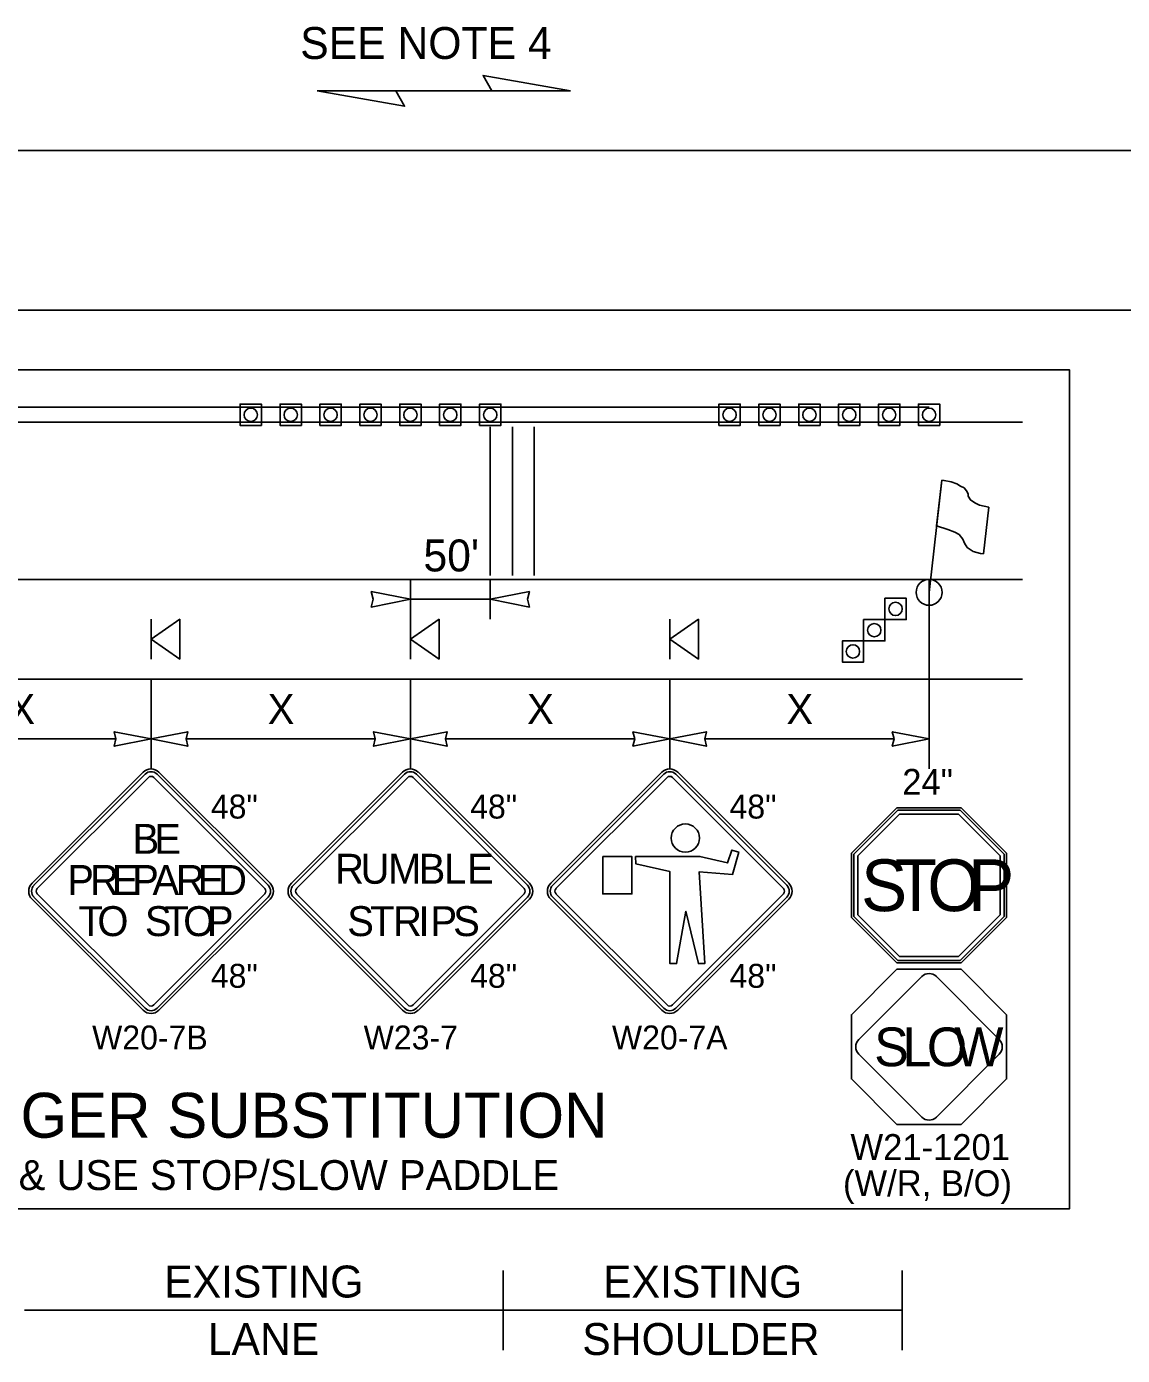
# Model space of a CAD drawing. Extents: x 99999.1 to 100095.7, y 99995 to 100010.7.
# Drawn here: x 100006.496 to 100009.243, y 100003.112 to 100006.443 of the extents above; entities that cross this region are included whole.
import ezdxf

# ---------------------------------------------------------------- set-up
doc = ezdxf.new("R2010")
doc.units = 0
for name, color, linetype in [('RD_ED_ShoulderPavedEdge', 7, 'Continuous'), ('RD_MK_LineDblYellowCenter', 7, 'Continuous'), ('RD_MK_LineEdgeWhite', 7, 'Continuous'), ('RD_MK_LineNoPass', 7, 'Continuous'), ('RD_MK_LineSkipCenter', 7, 'Continuous'), ('SH_DE_DetailHeading2Text', 7, 'Continuous'), ('TR_SN_ConstructionSigns', 7, 'Continuous'), ('TR_WZ_FlaggingStation', 7, 'Continuous'), ('TR_WZ_PortableSignMountBlk-Org', 7, 'Continuous'), ('TR_WZ_TrafficCone', 7, 'Continuous'), ('TR_WZ_WorkZoneDetails', 7, 'Continuous'), ('TR_WZ_WorkZoneTextCurrent', 7, 'Continuous')]:
    doc.layers.add(name, color=color, linetype=linetype)

msp = doc.modelspace()

# ---------------------------------------------------------------- linework, layer by layer
at = {"layer": 'RD_ED_ShoulderPavedEdge'}
for p, q in [((100000.1076, 100005.7323), (100015.6424, 100005.7323)), ((100005.2015, 100004.8073), (100008.9925, 100004.8073))]:
    msp.add_line(p, q, dxfattribs=at)
at = {"layer": 'RD_MK_LineDblYellowCenter'}
for p, q in [((100005.2015, 100005.4886), (100008.0081, 100005.4886)), ((100005.2015, 100005.4511), (100008.0081, 100005.4511))]:
    msp.add_line(p, q, dxfattribs=at)
at = {"layer": 'RD_MK_LineEdgeWhite'}
for p, q in [((100000.1076, 100006.1323), (100015.6424, 100006.1323)), ((100005.2015, 100005.0573), (100008.9925, 100005.0573))]:
    msp.add_line(p, q, dxfattribs=at)
at = {"layer": 'RD_MK_LineNoPass'}
msp.add_line((100008.0081, 100005.4886), (100008.7581, 100005.4886), dxfattribs=at)
at = {"layer": 'RD_MK_LineSkipCenter'}
msp.add_lwpolyline([(100008.9925, 100005.4511), (100008.0081, 100005.4511)], dxfattribs=at)
at = {"layer": 'TR_SN_ConstructionSigns'}
for p, q in [((100006.7882, 100004.5741), (100006.5098, 100004.2957)), ((100006.7932, 100004.5691), (100006.5147, 100004.2907)), ((100006.523, 100004.2824), (100006.8015, 100004.5608)), ((100006.8147, 100004.5608), (100007.0931, 100004.2824)), ((100007.1014, 100004.2907), (100006.823, 100004.5691)), ((100007.1064, 100004.2957), (100006.828, 100004.5741)), ((100007.4382, 100004.5741), (100007.1598, 100004.2957)), ((100007.4432, 100004.5691), (100007.1647, 100004.2907)), ((100007.173, 100004.2824), (100007.4515, 100004.5608)), ((100007.4647, 100004.5608), (100007.7431, 100004.2824)), ((100007.7514, 100004.2907), (100007.473, 100004.5691)), ((100007.7564, 100004.2957), (100007.478, 100004.5741)), ((100008.0882, 100004.5741), (100007.8098, 100004.2957)), ((100008.0932, 100004.5691), (100007.8147, 100004.2907)), ((100007.823, 100004.2824), (100008.1015, 100004.5608)), ((100008.1147, 100004.5608), (100008.3931, 100004.2824)), ((100008.4014, 100004.2907), (100008.123, 100004.5691)), ((100008.4064, 100004.2957), (100008.128, 100004.5741)), ((100008.6775, 100004.4851), (100008.5636, 100004.3713)), ((100008.68, 100004.4791), (100008.5697, 100004.3687)), ((100008.8385, 100004.4851), (100008.6775, 100004.4851)), ((100008.836, 100004.4791), (100008.68, 100004.4791)), ((100008.9463, 100004.3687), (100008.836, 100004.4791)), ((100008.9524, 100004.3713), (100008.8385, 100004.4851)), ((100008.5798, 100004.3646), (100008.6842, 100004.4689)), ((100008.6842, 100004.4689), (100008.8318, 100004.4689)), ((100008.8318, 100004.4689), (100008.9362, 100004.3646)), ((100008.5636, 100004.3713), (100008.5636, 100004.2102)), ((100008.5697, 100004.3687), (100008.5697, 100004.2127)), ((100008.5798, 100004.2169), (100008.5798, 100004.3646)), ((100008.9362, 100004.3646), (100008.9362, 100004.2169)), ((100008.9463, 100004.2127), (100008.9463, 100004.3687)), ((100008.9524, 100004.2102), (100008.9524, 100004.3713)), ((100006.5098, 100004.2559), (100006.7882, 100003.9775)), ((100006.5147, 100004.2609), (100006.7932, 100003.9824)), ((100006.8015, 100003.9907), (100006.523, 100004.2692)), ((100007.0931, 100004.2692), (100006.8147, 100003.9907)), ((100006.823, 100003.9824), (100007.1014, 100004.2609)), ((100006.828, 100003.9775), (100007.1064, 100004.2559)), ((100007.1598, 100004.2559), (100007.4382, 100003.9775)), ((100007.1647, 100004.2609), (100007.4432, 100003.9824)), ((100007.4515, 100003.9907), (100007.173, 100004.2692)), ((100007.7431, 100004.2692), (100007.4647, 100003.9907)), ((100007.473, 100003.9824), (100007.7514, 100004.2609)), ((100007.478, 100003.9775), (100007.7564, 100004.2559)), ((100007.8098, 100004.2559), (100008.0882, 100003.9775)), ((100007.8147, 100004.2609), (100008.0932, 100003.9824)), ((100008.1015, 100003.9907), (100007.823, 100004.2692)), ((100008.3931, 100004.2692), (100008.1147, 100003.9907)), ((100008.123, 100003.9824), (100008.4014, 100004.2609)), ((100008.128, 100003.9775), (100008.4064, 100004.2559)), ((100008.5636, 100004.2102), (100008.6775, 100004.0963)), ((100008.5697, 100004.2127), (100008.68, 100004.1024)), ((100008.6842, 100004.1125), (100008.5798, 100004.2169)), ((100008.9362, 100004.2169), (100008.8318, 100004.1125)), ((100008.836, 100004.1024), (100008.9463, 100004.2127)), ((100008.8385, 100004.0963), (100008.9524, 100004.2102)), ((100008.8318, 100004.1125), (100008.6842, 100004.1125)), ((100008.6775, 100004.0963), (100008.8385, 100004.0963)), ((100008.68, 100004.1024), (100008.836, 100004.1024)), ((100008.7397, 100004.0618), (100008.5819, 100003.9041)), ((100008.9341, 100003.9041), (100008.7763, 100004.0618)), ((100008.5819, 100003.8674), (100008.7397, 100003.7097)), ((100008.7763, 100003.7097), (100008.9341, 100003.8674))]:
    msp.add_line(p, q, dxfattribs=at)
for points in [[(100008.022, 100004.3628), (100008.023, 100004.3447), (100008.1085, 100004.3248), (100008.1085, 100004.0945), (100008.1252, 100004.0945), (100008.1487, 100004.2254), (100008.1799, 100004.0945), (100008.1957, 100004.0945), (100008.1819, 100004.3247), (100008.2654, 100004.318), (100008.2812, 100004.3738), (100008.264, 100004.3787), (100008.2529, 100004.3468), (100008.1839, 100004.3628)], [(100007.9404, 100004.3626), (100007.9404, 100004.269), (100008.0134, 100004.269), (100008.0134, 100004.3626)], [(100008.9524, 100003.9663), (100008.9524, 100003.8052), (100008.8385, 100003.6913), (100008.6775, 100003.6913), (100008.5636, 100003.8052), (100008.5636, 100003.9663), (100008.6775, 100004.0801), (100008.8385, 100004.0801)]]:
    msp.add_lwpolyline(points, close=True, dxfattribs=at)
msp.add_circle((100008.1472, 100004.4091), 0.0354, dxfattribs=at)
for centre, radius, start, end in [((100006.8081, 100004.5542), 0.0281, 45, 135), ((100006.8081, 100004.5542), 0.0211, 45, 135), ((100007.4581, 100004.5542), 0.0281, 45, 135), ((100007.4581, 100004.5542), 0.0211, 45, 135), ((100008.1081, 100004.5542), 0.0281, 45, 135), ((100008.1081, 100004.5542), 0.0211, 45, 135), ((100006.8081, 100004.5542), 0.00938, 45, 135), ((100007.4581, 100004.5542), 0.00938, 45, 135), ((100008.1081, 100004.5542), 0.00938, 45, 135), ((100006.5297, 100004.2758), 0.0281, 135, 225), ((100006.5297, 100004.2758), 0.0211, 135, 225), ((100006.5297, 100004.2758), 0.00938, 135, 225), ((100007.0865, 100004.2758), 0.00938, 315, 45), ((100007.0865, 100004.2758), 0.0211, 315, 45), ((100007.0865, 100004.2758), 0.0281, 315, 45), ((100007.1797, 100004.2758), 0.0281, 135, 225), ((100007.1797, 100004.2758), 0.0211, 135, 225), ((100007.1797, 100004.2758), 0.00938, 135, 225), ((100007.7365, 100004.2758), 0.00938, 315, 45), ((100007.7365, 100004.2758), 0.0211, 315, 45), ((100007.7365, 100004.2758), 0.0281, 315, 45), ((100007.8297, 100004.2758), 0.0281, 135, 225), ((100007.8297, 100004.2758), 0.0211, 135, 225), ((100007.8297, 100004.2758), 0.00938, 135, 225), ((100008.3865, 100004.2758), 0.00938, 315, 45), ((100008.3865, 100004.2758), 0.0211, 315, 45), ((100008.3865, 100004.2758), 0.0281, 315, 45), ((100008.758, 100004.0435), 0.0259, 45, 135), ((100006.8081, 100003.9974), 0.0281, 225, 315), ((100006.8081, 100003.9974), 0.0211, 225, 315), ((100006.8081, 100003.9974), 0.00938, 225, 315), ((100007.4581, 100003.9974), 0.0281, 225, 315), ((100007.4581, 100003.9974), 0.0211, 225, 315), ((100007.4581, 100003.9974), 0.00938, 225, 315), ((100008.1081, 100003.9974), 0.0281, 225, 315), ((100008.1081, 100003.9974), 0.0211, 225, 315), ((100008.1081, 100003.9974), 0.00938, 225, 315), ((100008.6003, 100003.8857), 0.0259, 135, 225), ((100008.9157, 100003.8857), 0.0259, 315, 45), ((100008.758, 100003.728), 0.0259, 225, 315)]:
    msp.add_arc(centre, radius, start, end, dxfattribs=at)
at = {"layer": 'TR_WZ_FlaggingStation'}
for p, q in [((100008.7581, 100005.0248), (100008.7901, 100005.3058)), ((100008.7771, 100005.1917), (100008.7902, 100005.3061)), ((100008.9081, 100005.2383), (100008.8948, 100005.1211)), ((100008.7771, 100005.1917), (100008.7771, 100005.1917))]:
    msp.add_line(p, q, dxfattribs=at)
for points in [[(100008.7902, 100005.3061), (100008.7959, 100005.3048), (100008.8137, 100005.3014), (100008.8276, 100005.2972), (100008.8372, 100005.2911), (100008.8458, 100005.2864), (100008.8515, 100005.2796), (100008.8557, 100005.2717), (100008.8562, 100005.2655), (100008.8616, 100005.2563), (100008.8724, 100005.2489), (100008.8848, 100005.2437), (100008.9081, 100005.2383)], [(100008.8948, 100005.1211), (100008.8867, 100005.1225), (100008.869, 100005.1271), (100008.8533, 100005.1376), (100008.8468, 100005.1482), (100008.8429, 100005.1585), (100008.8338, 100005.1694), (100008.8229, 100005.1756), (100008.8055, 100005.1827), (100008.7771, 100005.1917)]]:
    msp.add_lwpolyline(points, dxfattribs=at)
msp.add_circle((100008.7581, 100005.0248), 0.0325, dxfattribs=at)
at = {"layer": 'TR_WZ_PortableSignMountBlk-Org'}
for p, q in [((100006.8081, 100004.8574), (100006.8081, 100004.9574)), ((100007.4581, 100004.8574), (100007.4581, 100004.9574)), ((100008.1081, 100004.8574), (100008.1081, 100004.9574))]:
    msp.add_line(p, q, dxfattribs=at)
for points in [[(100006.8081, 100004.9073), (100006.8799, 100004.9574), (100006.8799, 100004.8574)], [(100007.4581, 100004.9073), (100007.5299, 100004.9574), (100007.5299, 100004.8574)], [(100008.1081, 100004.9073), (100008.1799, 100004.9574), (100008.1799, 100004.8574)]]:
    msp.add_lwpolyline(points, close=True, dxfattribs=at)
at = {"layer": 'TR_WZ_TrafficCone'}
for points in [[(100007.0848, 100005.4965), (100007.0314, 100005.4965), (100007.0314, 100005.4432), (100007.0848, 100005.4432), (100007.0848, 100005.4965)], [(100007.0848, 100005.4432), (100007.0314, 100005.4432), (100007.0314, 100005.4965), (100007.0848, 100005.4965), (100007.0848, 100005.4432)], [(100007.1848, 100005.4965), (100007.1314, 100005.4965), (100007.1314, 100005.4432), (100007.1848, 100005.4432), (100007.1848, 100005.4965)], [(100007.1848, 100005.4432), (100007.1314, 100005.4432), (100007.1314, 100005.4965), (100007.1848, 100005.4965), (100007.1848, 100005.4432)], [(100007.2848, 100005.4965), (100007.2314, 100005.4965), (100007.2314, 100005.4432), (100007.2848, 100005.4432), (100007.2848, 100005.4965)], [(100007.2848, 100005.4432), (100007.2314, 100005.4432), (100007.2314, 100005.4965), (100007.2848, 100005.4965), (100007.2848, 100005.4432)], [(100007.3848, 100005.4965), (100007.3314, 100005.4965), (100007.3314, 100005.4432), (100007.3848, 100005.4432), (100007.3848, 100005.4965)], [(100007.3848, 100005.4432), (100007.3314, 100005.4432), (100007.3314, 100005.4965), (100007.3848, 100005.4965), (100007.3848, 100005.4432)], [(100007.4848, 100005.4965), (100007.4314, 100005.4965), (100007.4314, 100005.4432), (100007.4848, 100005.4432), (100007.4848, 100005.4965)], [(100007.4848, 100005.4432), (100007.4314, 100005.4432), (100007.4314, 100005.4965), (100007.4848, 100005.4965), (100007.4848, 100005.4432)], [(100007.5848, 100005.4965), (100007.5314, 100005.4965), (100007.5314, 100005.4432), (100007.5848, 100005.4432), (100007.5848, 100005.4965)], [(100007.5848, 100005.4432), (100007.5314, 100005.4432), (100007.5314, 100005.4965), (100007.5848, 100005.4965), (100007.5848, 100005.4432)], [(100007.6848, 100005.4965), (100007.6314, 100005.4965), (100007.6314, 100005.4432), (100007.6848, 100005.4432), (100007.6848, 100005.4965)], [(100007.6848, 100005.4432), (100007.6314, 100005.4432), (100007.6314, 100005.4965), (100007.6848, 100005.4965), (100007.6848, 100005.4432)], [(100008.2848, 100005.4965), (100008.2314, 100005.4965), (100008.2314, 100005.4432), (100008.2848, 100005.4432), (100008.2848, 100005.4965)], [(100008.2848, 100005.4432), (100008.2314, 100005.4432), (100008.2314, 100005.4965), (100008.2848, 100005.4965), (100008.2848, 100005.4432)], [(100008.3848, 100005.4965), (100008.3314, 100005.4965), (100008.3314, 100005.4432), (100008.3848, 100005.4432), (100008.3848, 100005.4965)], [(100008.3848, 100005.4432), (100008.3314, 100005.4432), (100008.3314, 100005.4965), (100008.3848, 100005.4965), (100008.3848, 100005.4432)], [(100008.4848, 100005.4965), (100008.4314, 100005.4965), (100008.4314, 100005.4432), (100008.4848, 100005.4432), (100008.4848, 100005.4965)], [(100008.4848, 100005.4432), (100008.4314, 100005.4432), (100008.4314, 100005.4965), (100008.4848, 100005.4965), (100008.4848, 100005.4432)], [(100008.5848, 100005.4965), (100008.5314, 100005.4965), (100008.5314, 100005.4432), (100008.5848, 100005.4432), (100008.5848, 100005.4965)], [(100008.5848, 100005.4432), (100008.5314, 100005.4432), (100008.5314, 100005.4965), (100008.5848, 100005.4965), (100008.5848, 100005.4432)], [(100008.6848, 100005.4965), (100008.6314, 100005.4965), (100008.6314, 100005.4432), (100008.6848, 100005.4432), (100008.6848, 100005.4965)], [(100008.6848, 100005.4432), (100008.6314, 100005.4432), (100008.6314, 100005.4965), (100008.6848, 100005.4965), (100008.6848, 100005.4432)], [(100008.7848, 100005.4965), (100008.7314, 100005.4965), (100008.7314, 100005.4432), (100008.7848, 100005.4432), (100008.7848, 100005.4965)], [(100008.7848, 100005.4432), (100008.7314, 100005.4432), (100008.7314, 100005.4965), (100008.7848, 100005.4965), (100008.7848, 100005.4432)], [(100008.6474, 100005.01), (100008.7008, 100005.01), (100008.7008, 100004.9567), (100008.6474, 100004.9567), (100008.6474, 100005.01)], [(100008.6474, 100004.9567), (100008.7008, 100004.9567), (100008.7008, 100005.01), (100008.6474, 100005.01), (100008.6474, 100004.9567)], [(100008.5941, 100004.9567), (100008.6474, 100004.9567), (100008.6474, 100004.9033), (100008.5941, 100004.9033), (100008.5941, 100004.9567)], [(100008.5941, 100004.9033), (100008.6474, 100004.9033), (100008.6474, 100004.9567), (100008.5941, 100004.9567), (100008.5941, 100004.9033)], [(100008.5408, 100004.9033), (100008.5941, 100004.9033), (100008.5941, 100004.85), (100008.5408, 100004.85), (100008.5408, 100004.9033)], [(100008.5408, 100004.85), (100008.5941, 100004.85), (100008.5941, 100004.9033), (100008.5408, 100004.9033), (100008.5408, 100004.85)]]:
    msp.add_lwpolyline(points, dxfattribs=at)
for centre in [(100007.0581, 100005.4698), (100007.1581, 100005.4698), (100007.2581, 100005.4698), (100007.3581, 100005.4698), (100007.4581, 100005.4698), (100007.5581, 100005.4698), (100007.6581, 100005.4698), (100008.2581, 100005.4698), (100008.3581, 100005.4698), (100008.4581, 100005.4698), (100008.5581, 100005.4698), (100008.6581, 100005.4698), (100008.7581, 100005.4698), (100008.6741, 100004.9833), (100008.6208, 100004.93), (100008.5674, 100004.8767)]:
    msp.add_circle(centre, 0.0167, dxfattribs=at)
at = {"layer": 'TR_WZ_WorkZoneDetails'}
for p, q in [((100007.4213, 100006.2816), (100007.6624, 100006.2816)), ((100007.6624, 100006.2816), (100007.4213, 100006.2816)), ((100007.6581, 100005.0673), (100007.6581, 100005.4398)), ((100007.7137, 100005.0673), (100007.7137, 100005.4398)), ((100007.7686, 100005.0673), (100007.7686, 100005.4398)), ((100007.4581, 100004.9574), (100007.4581, 100005.0573)), ((100007.6581, 100005.0573), (100007.6581, 100004.9574)), ((100008.7581, 100005.0573), (100008.7581, 100004.5823)), ((100007.6581, 100005.0074), (100007.4581, 100005.0074)), ((100006.8081, 100004.8073), (100006.8081, 100004.5823)), ((100007.4581, 100004.8073), (100007.4581, 100004.5823)), ((100008.1081, 100004.8073), (100008.1081, 100004.5823)), ((100006.7202, 100004.6573), (100006.246, 100004.6573)), ((100007.3702, 100004.6573), (100006.896, 100004.6573)), ((100008.0202, 100004.6573), (100007.546, 100004.6573)), ((100008.6702, 100004.6573), (100008.196, 100004.6573)), ((100007.6907, 100003.1255), (100007.6907, 100003.3255)), ((100008.6907, 100003.1255), (100008.6907, 100003.3255)), ((100006.4907, 100003.2255), (100007.6907, 100003.2255)), ((100007.6907, 100003.2255), (100008.6907, 100003.2255))]:
    msp.add_line(p, q, dxfattribs=at)
for points in [[(100007.859, 100006.2816), (100007.6401, 100006.3202), (100007.6624, 100006.2816)], [(100007.2248, 100006.2816), (100007.4436, 100006.243), (100007.4213, 100006.2816)], [(100007.4581, 100005.0074), (100007.3598, 100004.9881), (100007.3644, 100005.0074), (100007.3598, 100005.0267)], [(100007.6581, 100005.0074), (100007.7564, 100004.9881), (100007.7518, 100005.0074), (100007.7564, 100005.0267)], [(100006.8081, 100004.6573), (100006.7159, 100004.6754), (100006.7202, 100004.6573), (100006.7159, 100004.6393)], [(100006.8081, 100004.6573), (100006.9002, 100004.6754), (100006.896, 100004.6573), (100006.9002, 100004.6393)], [(100007.4581, 100004.6573), (100007.3659, 100004.6754), (100007.3702, 100004.6573), (100007.3659, 100004.6393)], [(100007.4581, 100004.6573), (100007.5502, 100004.6754), (100007.546, 100004.6573), (100007.5502, 100004.6393)], [(100008.1081, 100004.6573), (100008.0159, 100004.6754), (100008.0202, 100004.6573), (100008.0159, 100004.6393)], [(100008.1081, 100004.6573), (100008.2002, 100004.6754), (100008.196, 100004.6573), (100008.2002, 100004.6393)], [(100008.7581, 100004.6573), (100008.6659, 100004.6754), (100008.6702, 100004.6573), (100008.6659, 100004.6393)]]:
    msp.add_lwpolyline(points, close=True, dxfattribs=at)
at = {"layer": 'TR_WZ_WorkZoneTextCurrent'}
msp.add_lwpolyline([(100005.1015, 100005.5823), (100009.1102, 100005.5823), (100009.1102, 100003.4799), (100005.1015, 100003.4799)], close=True, dxfattribs=at)

# ---------------------------------------------------------------- texts
at = {"layer": 'SH_DE_DetailHeading2Text'}
msp.add_text('HUMAN FLAGGER SUBSTITUTION', height=0.1125, rotation=360, dxfattribs=at).set_placement((100005.4946, 100003.658))
at = {"layer": 'TR_SN_ConstructionSigns'}
for s, height, p in [('24"', 0.0648, (100008.6908, 100004.5175)), ('B', 0.075, (100006.7616, 100004.3695)), ('E', 0.075, (100006.8163, 100004.3695)), ('R', 0.075, (100007.2695, 100004.2945)), ('U', 0.075, (100007.3332, 100004.2945)), ('M', 0.075, (100007.4022, 100004.2945)), ('B', 0.075, (100007.4787, 100004.2945)), ('L', 0.075, (100007.5425, 100004.2945)), ('E', 0.075, (100007.6002, 100004.2945)), ('S', 0.1296, (100008.5876, 100004.2259)), ('T', 0.1296, (100008.6718, 100004.2259)), ('O', 0.1296, (100008.7535, 100004.2259)), ('P', 0.1296, (100008.8559, 100004.2259)), ('P', 0.075, (100006.5981, 100004.2664)), ('R', 0.075, (100006.6551, 100004.2664)), ('E', 0.075, (100006.7098, 100004.2664)), ('P', 0.075, (100006.7608, 100004.2664)), ('A', 0.075, (100006.8118, 100004.2664)), ('R', 0.075, (100006.8703, 100004.2664)), ('E', 0.075, (100006.9251, 100004.2664)), ('D', 0.075, (100006.9761, 100004.2664)), ('T', 0.075, (100006.6262, 100004.1633)), ('O', 0.075, (100006.6735, 100004.1633)), ('S', 0.075, (100006.7927, 100004.1633)), ('T', 0.075, (100006.8415, 100004.1633)), ('O', 0.075, (100006.8887, 100004.1633)), ('P', 0.075, (100006.948, 100004.1633)), ('S', 0.075, (100007.2998, 100004.1633)), ('T', 0.075, (100007.3568, 100004.1633)), ('R', 0.075, (100007.4146, 100004.1633)), ('I', 0.075, (100007.4783, 100004.1633)), ('P', 0.075, (100007.5083, 100004.1633)), ('S', 0.075, (100007.5653, 100004.1633)), ('S', 0.0972, (100008.6205, 100003.8371)), ('L', 0.0972, (100008.6914, 100003.8371)), ('O', 0.0972, (100008.7527, 100003.8371)), ('W', 0.0972, (100008.8217, 100003.8371))]:
    msp.add_text(s, height=height, dxfattribs=at).set_placement(p)
for s, height, p in [('48"', 0.06, (100006.9579, 100004.4579)), ('48"', 0.06, (100007.6079, 100004.4579)), ('48"', 0.06, (100008.2579, 100004.4579)), ('48"', 0.06, (100006.9579, 100004.0337)), ('48"', 0.06, (100007.6079, 100004.0337)), ('48"', 0.06, (100008.2579, 100004.0337)), ('W20-7B', 0.06, (100006.6603, 100003.8792)), ('W23-7', 0.06, (100007.3409, 100003.8792)), ('W20-7A', 0.06, (100007.9632, 100003.8792)), ('W21-1201', 0.0648, (100008.5611, 100003.6022)), ('(W/R, B/O)', 0.0648, (100008.5423, 100003.5115))]:
    msp.add_text(s, height=height, rotation=360, dxfattribs=at).set_placement(p)
at = {"layer": 'TR_WZ_WorkZoneDetails'}
for s, p in [('EXISTING', (100006.8409, 100003.2575)), ('EXISTING', (100007.9409, 100003.2575)), ('LANE', (100006.9503, 100003.1135)), ('SHOULDER', (100007.889, 100003.1135))]:
    msp.add_text(s, height=0.08, rotation=360, dxfattribs=at).set_placement(p)
at = {"layer": 'TR_WZ_WorkZoneTextCurrent'}
for s, height, p in [('SEE NOTE 4', 0.08, (100007.1819, 100006.3616)), ("50'", 0.08, (100007.4908, 100005.0773)), ('UPDATE SIGNAGE & USE STOP/SLOW PADDLE', 0.075, (100005.5568, 100003.5268))]:
    msp.add_text(s, height=height, dxfattribs=at).set_placement(p)
for p in [(100006.4505, 100004.6948), (100007.1005, 100004.6948), (100007.7505, 100004.6948), (100008.4005, 100004.6948)]:
    msp.add_text('X', height=0.075, rotation=360, dxfattribs=at).set_placement(p)

doc.saveas('drawing.dxf')
